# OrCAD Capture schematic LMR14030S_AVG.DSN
size E; title: LMR14030 SIMPLE SWITCHER® 40 V 3.5 A, 2.2 MHz Step-Down; rev: 1.0; note: Datasheet: SNVSA81A     EVM: SNVU462A; note: Synchronous Step Down Converter
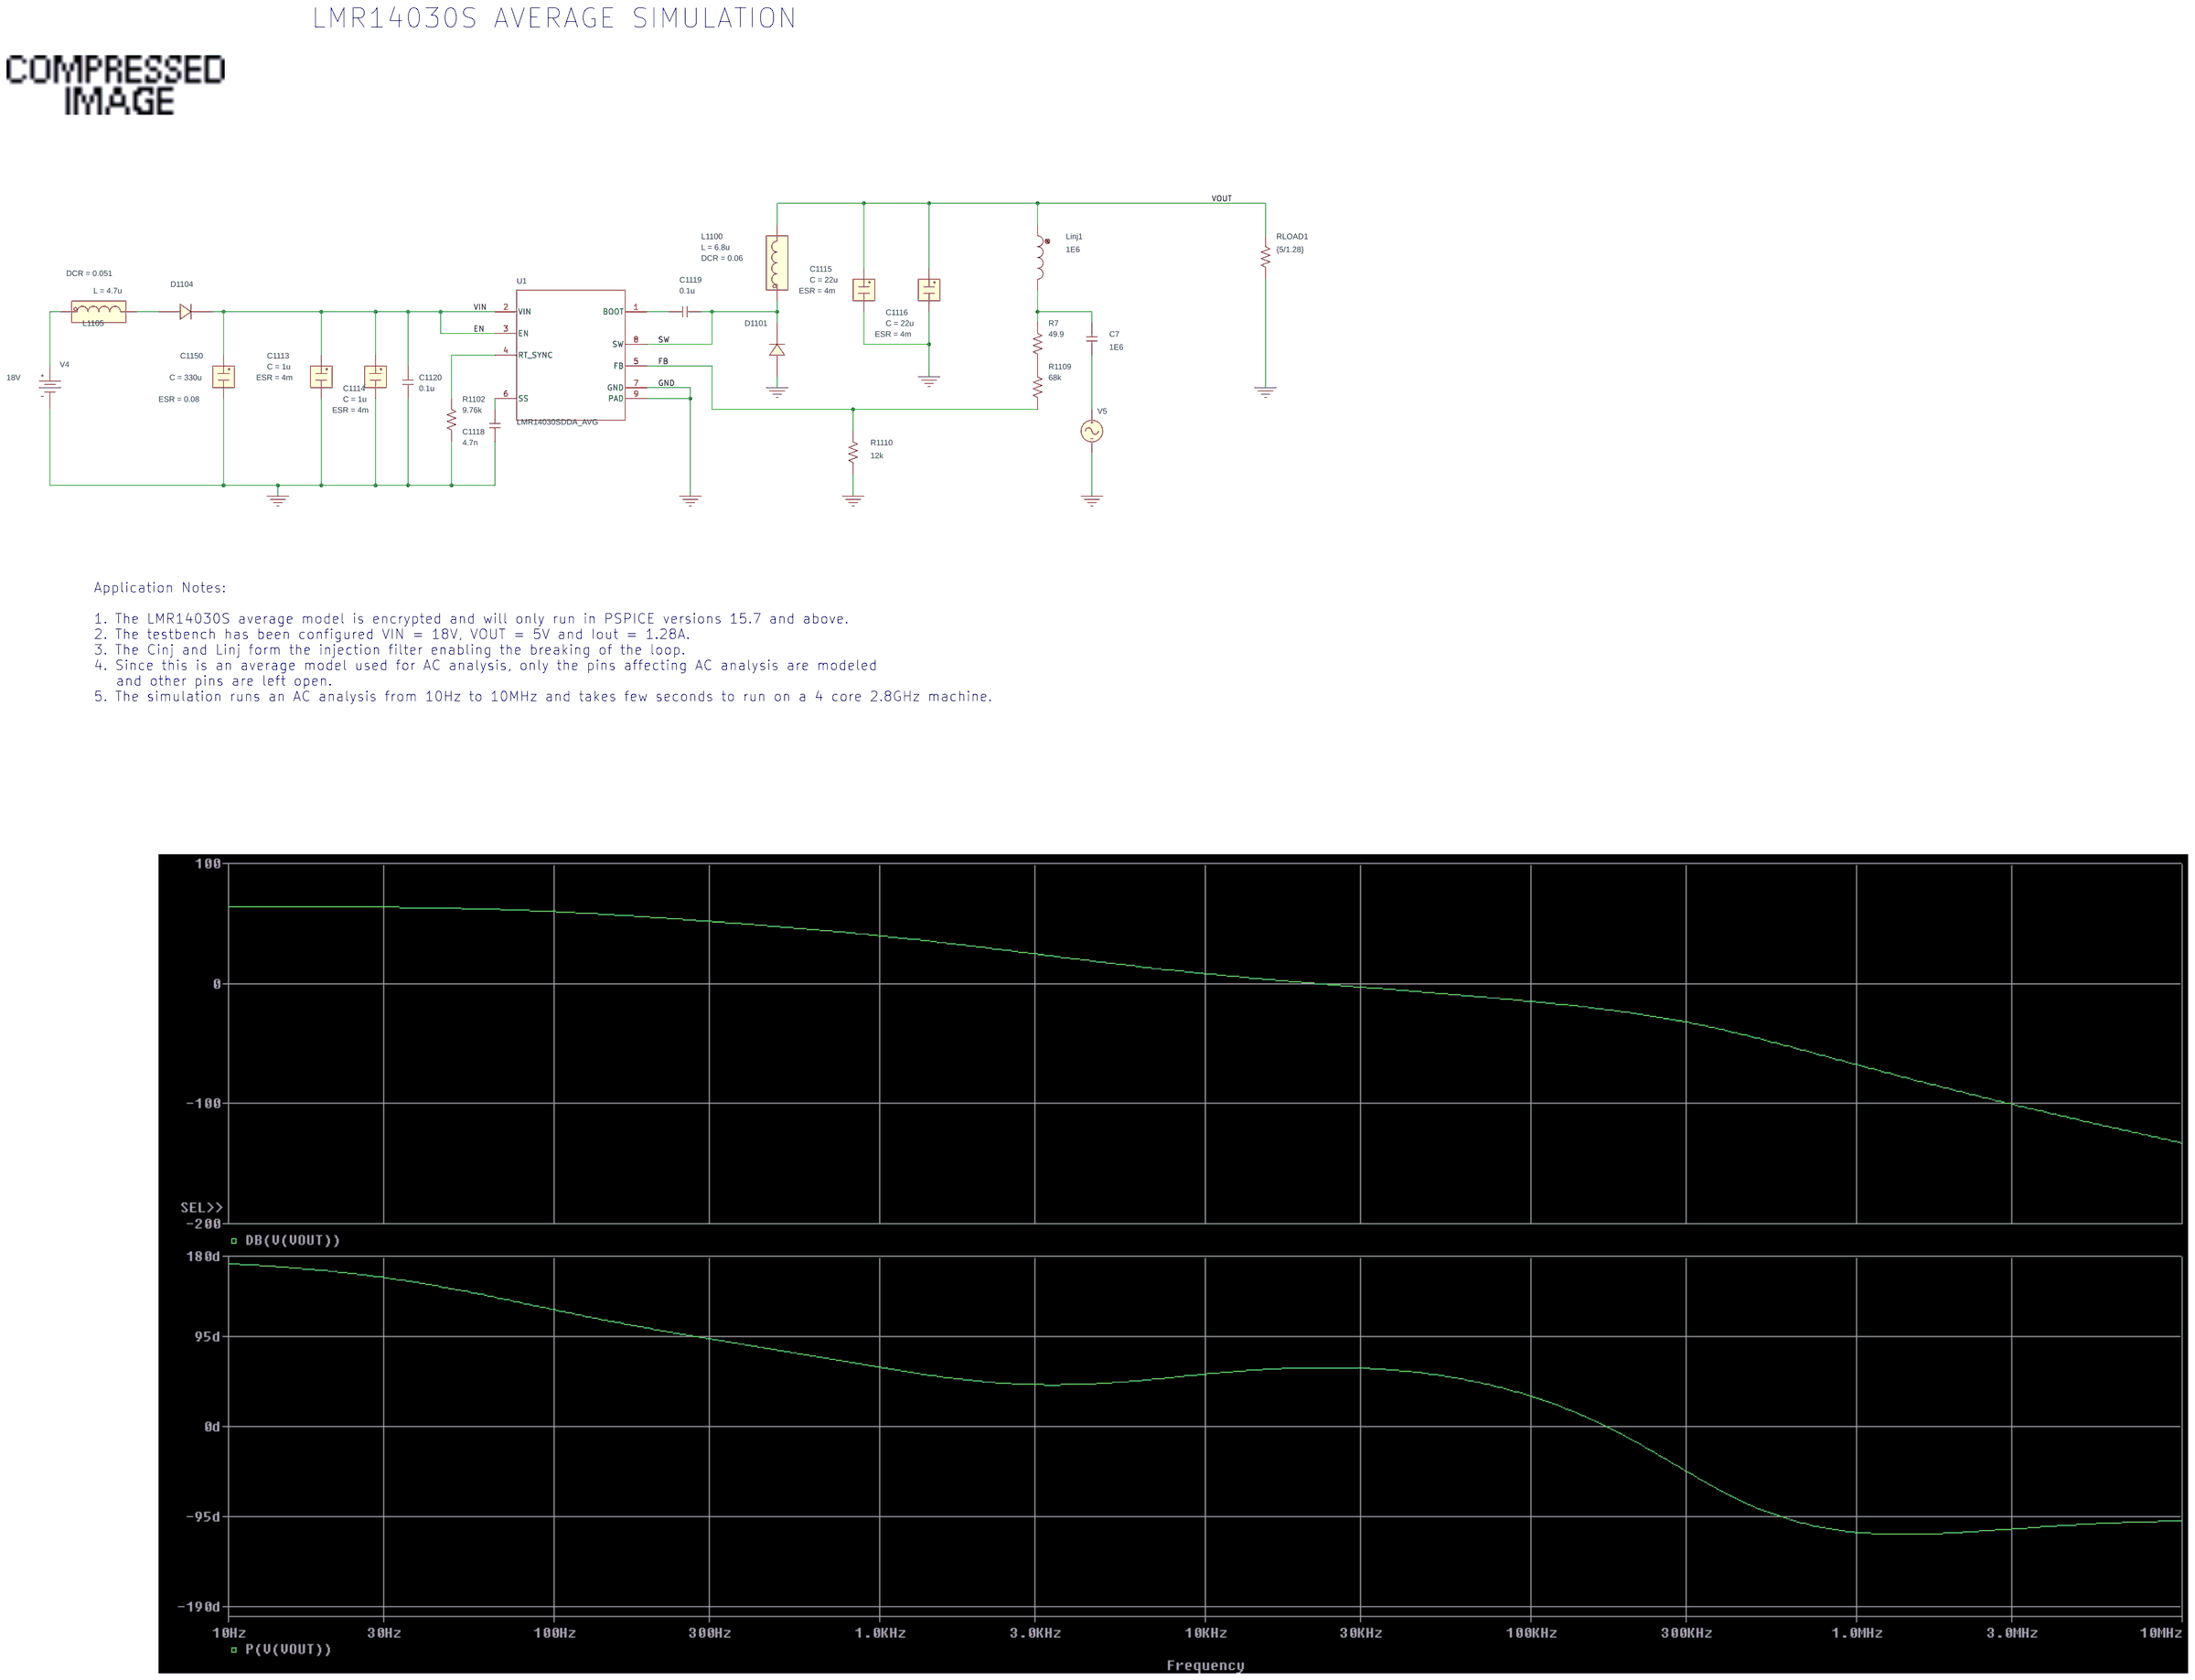
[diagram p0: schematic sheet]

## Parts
C7  1E6  [RAD/CK05]
C1113  CESR
C1114  CESR
C1115  CESR
C1116  CESR
C1118  4.7n  [RAD/CK05]
C1119  0.1u  [RAD/CK05]
C1120  0.1u  [RAD/CK05]
C1150  CESR
D1101  D_D1
D1104  DMURS220T3  [DO41]
L1100  LDCR
L1105  LDCR
Linj1  1E6  [DISC/.350x.175/LS.200x.100/.034]
R7  49.9  [AX/RC05]
R1102  9.76k  [AX/RC05]
R1109  68k  [AX/RC05]
R1110  12k  [AX/RC05]
RLOAD1  {5/1.28}  [AX/RC05]
U1  LMR14030SDDA_AVG  [DDA0008E_N]
V4  VDC
V5  VAC

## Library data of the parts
C7 C1118-C1120 = C
C1113 C1114 = CESR: C: 1u; ESR: 4m; PSpiceTemplate: X^@REFDES %IN %OUT @MODEL PARAMS:  ?C|C=@C||C=100u|  ?ESR|ESR=@ESR||ESR=0.01| ?X|X=@X||X=2|  ?IC|IC=@IC||IC=2|; X: 1
C1115 C1116 = CESR: C: 22u; ESR: 4m; PSpiceTemplate: X^@REFDES %IN %OUT @MODEL PARAMS:  ?C|C=@C||C=100u|  ?ESR|ESR=@ESR||ESR=0.01| ?X|X=@X||X=2|  ?IC|IC=@IC||IC=2|; X: 1
C1150 = CESR: C: 330u; ESR: 0.08; IC: 5; PSpiceTemplate: X^@REFDES %IN %OUT @MODEL PARAMS:  ?C|C=@C||C=100u|  ?ESR|ESR=@ESR||ESR=0.01| ?X|X=@X||X=2|  ?IC|IC=@IC||IC=2|; X: 1
D1101 = D_D1
D1104 = DMURS220T3
L1100 = LDCR_1: DCR: 0.06; IC: 0; L: 6.8u; PSpiceTemplate: X^@REFDES %IN %OUT @MODEL PARAMS:  ?L|L=@L||L=1u|  ?DCR|DCR=@DCR||DCR=0.01| ?IC|IC=@IC||IC=0|
L1105 = LDCR: DCR: 0.051; IC: 0; L: 4.7u; PSpiceTemplate: X^@REFDES %IN %OUT @MODEL PARAMS:  ?L|L=@L||L=1u|  ?DCR|DCR=@DCR||DCR=0.01| ?IC|IC=@IC||IC=0|
Linj1 = L
R7 R1102 R1109 R1110 RLOAD1 = R
U1 = LMR14030SDDA_AVG: FS_p: 2.2MHz; L_p: 6.8u; VOUT_p: 5
V4 = VDC: DC: 18V
V5 = VAC

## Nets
0: C1113.3(OUT) C1114.3(OUT) C1115.3(OUT) C1116.3(OUT) C1118.1 C1120.1 C1150.3(OUT) D1101.2(A) R1102.1 R1110.1 RLOAD1.1 U1.7(GND) U1.9(PAD) V4.1(-) V5.2(-)
EN: C1113.1(IN) C1114.1(IN) C1120.2 C1150.1(IN) D1104.1(C) U1.2(VIN) U1.3(EN)
FB: R1109.1 R1110.2 U1.5(FB)
SW: C1119.1 D1101.1(C) L1100.1(IN) U1.8(SW)
VOUT: C1115.1(IN) C1116.1(IN) L1100.3(OUT) Linj1.1 RLOAD1.2
N16777768: L1105.1(IN) V4.0(+)
N16777867: R1102.2 U1.4(RT_SYNC)
N16795438: C1119.2 U1.1(BOOT)
N16798099: C1118.2 U1.6(SS)
N16811372: C7.2 Linj1.2 R7.2
N16833845: D1104.2(A) L1105.3(OUT)
N16843010: R7.1 R1109.2
N16843472: C7.1 V5.1(+)

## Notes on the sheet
- LMR14030S AVERAGE SIMULATION
- Application Notes:
  1. The LMR14030S average model is encrypted and will only run in PSPICE versions 15.7 and above.
  2. The testbench has been configured VIN = 18V, VOUT = 5V and Iout = 1.28A.
  3. The Cinj and Linj form the injection filter enabling the breaking of the loop.
  4. Since this is an average model used for AC analysis, only the pins affecting AC analysis are modeled
     and other pins are left open.
  5. The simulation runs an AC analysis from 10Hz to 10MHz and takes few seconds to run on a 4 core 2.8GHz machine.
